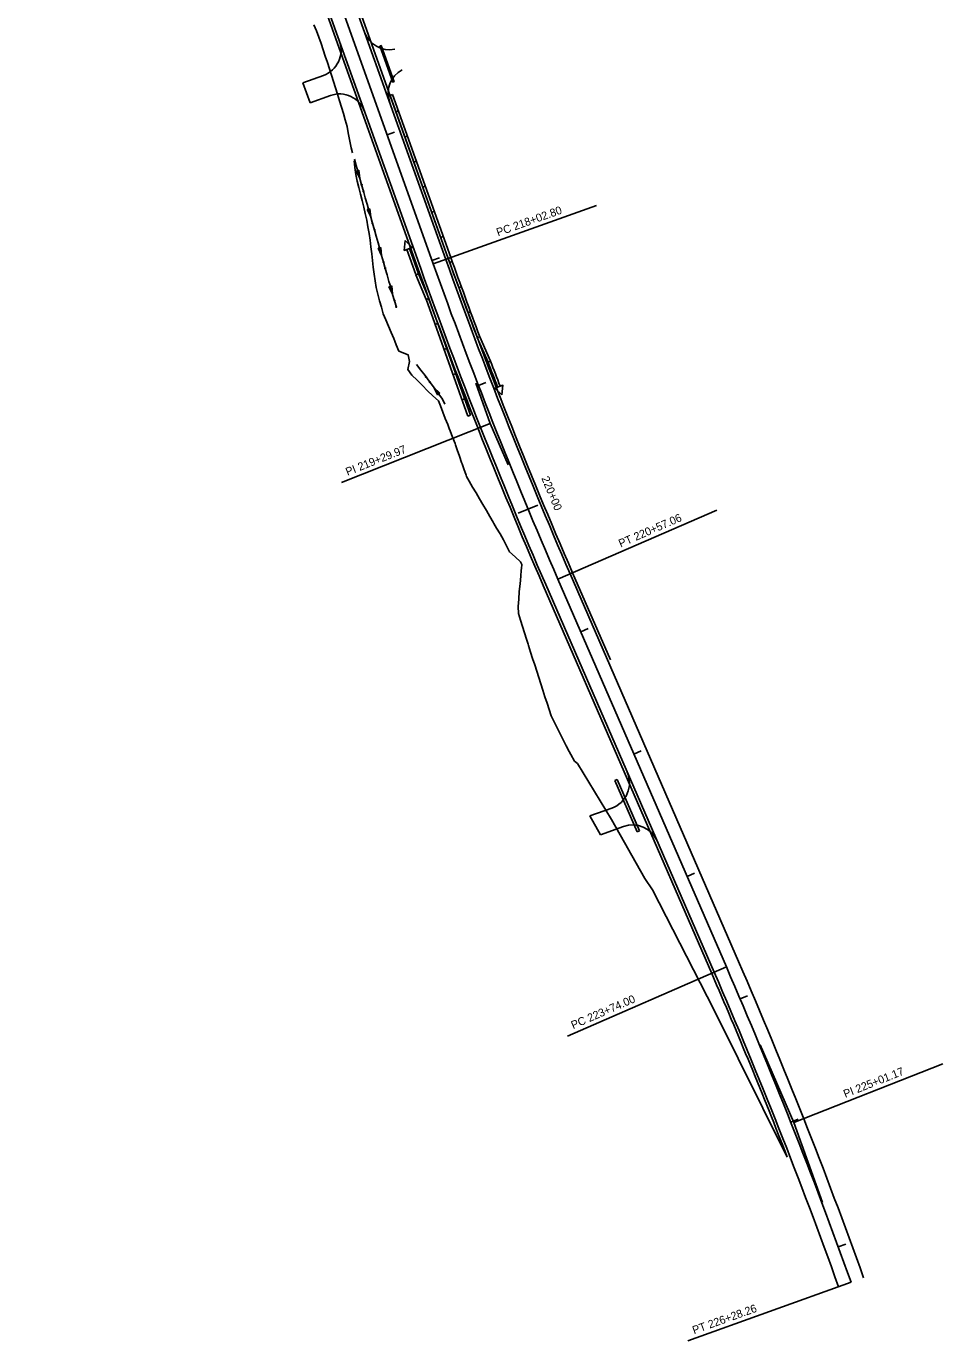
# Model space of a CAD drawing. Extents: x 1051958 to 1052837, y 395840 to 397825.
# Drawn here: x 1052150 to 1052837, y 395840 to 396826 of the extents above; entities that cross this region are included whole.
import ezdxf

# ---------------------------------------------------------------- set-up
doc = ezdxf.new("R2010")
doc.units = 0
for name, color, linetype in [('MOT_PCCB', 7, 'Continuous'), ('MOT_TIAB', 7, 'Continuous'), ('R_Drainage_Temporary', 7, 'Continuous'), ('R_Horz Alg Annot_Detour', 7, 'Continuous'), ('R_Horz Alg Stationing_Detour', 7, 'Continuous'), ('R_Horz Alg_Detour', 7, 'Continuous'), ('R_Proposed Const Limits', 7, 'Continuous'), ('R_Proposed Road_Detour', 7, 'Continuous'), ('R_Shld_Detour', 7, 'Continuous'), ('R_Special Ditch', 7, 'Continuous')]:
    doc.layers.add(name, color=color, linetype=linetype)

msp = doc.modelspace()

# ---------------------------------------------------------------- linework, layer by layer
at = {"layer": 'MOT_PCCB'}
for p, q in [((1052422.41, 396773.92), (1052424.29, 396774.59)), ((1052422.41, 396773.92), (1052466.12, 396651.7)), ((1052424.29, 396774.59), (1052468, 396652.38)), ((1052426.79, 396761.68), (1052428.67, 396762.35)), ((1052433.52, 396742.85), (1052435.41, 396743.52)), ((1052440.26, 396724.02), (1052442.14, 396724.69)), ((1052446.99, 396705.18), (1052448.88, 396705.86)), ((1052453.73, 396686.35), (1052455.61, 396687.02)), ((1052460.46, 396667.52), (1052462.34, 396668.19)), ((1052441.84, 396639.62), (1052435.1, 396658.45)), ((1052443.72, 396640.29), (1052436.99, 396659.12)), ((1052467.2, 396648.69), (1052469.08, 396649.36)), ((1052443.72, 396640.29), (1052441.84, 396639.62)), ((1052443.72, 396640.29), (1052441.88, 396639.53)), ((1052449.55, 396621.03), (1052441.88, 396639.53)), ((1052451.4, 396621.8), (1052443.72, 396640.29)), ((1052473.93, 396629.86), (1052475.81, 396630.53)), ((1052451.4, 396621.8), (1052449.52, 396621.12)), ((1052480.83, 396533.56), (1052449.52, 396621.12)), ((1052451.4, 396621.8), (1052449.55, 396621.03)), ((1052482.71, 396534.23), (1052451.4, 396621.8)), ((1052480.9, 396611.11), (1052482.78, 396611.78)), ((1052458.13, 396602.97), (1052456.25, 396602.29)), ((1052464.87, 396584.13), (1052462.98, 396583.46)), ((1052487.89, 396592.37), (1052489.78, 396593.04)), ((1052487.89, 396592.37), (1052495.93, 396574)), ((1052489.78, 396593.04), (1052497.82, 396574.68)), ((1052495.93, 396574), (1052497.82, 396574.68)), ((1052471.6, 396565.3), (1052469.72, 396564.63)), ((1052503.13, 396555.34), (1052505.01, 396556.01)), ((1052478.34, 396546.47), (1052476.45, 396545.8)), ((1052482.71, 396534.23), (1052480.83, 396533.56))]:
    msp.add_line(p, q, dxfattribs=at)
for radius, start, end in [(3807.72, 199.67806, 200.62965), (3805.72, 199.67806, 200.62965), (3806.72, 200.93048, 201.2316), (3804.72, 200.93114, 201.23242)]:
    msp.add_arc((1056051.46, 397933.9), radius, start, end, dxfattribs=at)
at = {"layer": 'MOT_TIAB'}
for points in [[(1052433.8, 396665.07), (1052439, 396659.84), (1052433.09, 396657.73)], [(1052506.32, 396549.39), (1052501.12, 396554.62), (1052507.02, 396556.73)]]:
    msp.add_lwpolyline(points, close=True, dxfattribs=at)
at = {"layer": 'R_Drainage_Temporary'}
for p, q in [((1052414.79, 396811.15), (1052415.74, 396811.49)), ((1052414.79, 396811.15), (1052424.62, 396783.86)), ((1052415.74, 396811.49), (1052425.56, 396784.2)), ((1052424.62, 396783.86), (1052425.56, 396784.2)), ((1052592.84, 396261.23), (1052591, 396260.44)), ((1052607.74, 396221.92), (1052591, 396260.44)), ((1052609.58, 396222.72), (1052592.84, 396261.23)), ((1052607.74, 396221.92), (1052609.58, 396222.72))]:
    msp.add_line(p, q, dxfattribs=at)
at = {"layer": 'R_Horz Alg Annot_Detour'}
for p, q in [((1052497.64, 396527.91), (1052486.79, 396558.25)), ((1052497.64, 396527.91), (1052511.08, 396497)), ((1052725.37, 396003.97), (1052700.02, 396062.29)), ((1052725.37, 396003.97), (1052746.78, 395944.1))]:
    msp.add_line(p, q, dxfattribs=at)
for points in [[(1052454.82, 396647.66), (1052577.23, 396691.44)], [(1052497.64, 396527.91), (1052386.06, 396483.77)], [(1052548.34, 396411.28), (1052667.56, 396463.1)], [(1052674.68, 396120.61), (1052555.45, 396068.79)], [(1052725.37, 396003.97), (1052836.96, 396048.12)], [(1052768.2, 395884.22), (1052645.79, 395840.45)]]:
    msp.add_lwpolyline(points, dxfattribs=at)
at = {"layer": 'R_Horz Alg Stationing_Detour'}
for p, q in [((1052610.82, 396282.57), (1052605.32, 396280.18)), ((1052650.68, 396190.86), (1052645.18, 396188.47)), ((1052690.48, 396099.08), (1052684.96, 396096.72)), ((1052728.57, 396006.45), (1052722.99, 396004.24)), ((1052764.22, 395912.86), (1052758.58, 395910.79))]:
    msp.add_line(p, q, dxfattribs=at)
for points in [[(1052425.85, 396746.48), (1052420.2, 396744.46)], [(1052459.53, 396652.32), (1052453.88, 396650.3)], [(1052494.31, 396558.73), (1052488.71, 396556.56)], [(1052533.37, 396466.85), (1052518.6, 396460.69)], [(1052570.96, 396374.28), (1052565.46, 396371.89)]]:
    msp.add_lwpolyline(points, dxfattribs=at)
at = {"layer": 'R_Horz Alg_Detour'}
for p, q in [((1052160.88, 397469.61), (1052454.82, 396647.66)), ((1052548.34, 396411.28), (1052674.68, 396120.61))]:
    msp.add_line(p, q, dxfattribs=at)
for centre, start, end in [((1056051.46, 397933.9), 199.67806, 203.49194), ((1049171.55, 394597.99), 19.67806, 23.49194)]:
    msp.add_arc(centre, 3819.72, start, end, dxfattribs=at)
at = {"layer": 'R_Proposed Const Limits'}
msp.add_line((1052665.37, 396088.72), (1052720.38, 395978.04), dxfattribs=at)
for points in [[(1052365.33, 396826.85), (1052367.38, 396822.27), (1052369.1, 396817.58), (1052370.81, 396812.88), (1052372.36, 396808.13), (1052373.87, 396803.36), (1052375.42, 396798.6), (1052376.97, 396793.84), (1052378.47, 396789.07), (1052380.05, 396784.32), (1052381.57, 396779.56), (1052383.08, 396774.79), (1052384.54, 396770), (1052385.99, 396765.21), (1052387.44, 396760.42), (1052388.88, 396755.62), (1052390.15, 396750.77), (1052391.13, 396745.81), (1052392.04, 396740.82), (1052392.95, 396735.84), (1052393.14, 396734.78), (1052394.25, 396730.99)], [(1052395.41, 396724.88), (1052396.07, 396719.81), (1052396.86, 396714.78), (1052397.76, 396709.79), (1052398.96, 396704.91), (1052400.18, 396700.04), (1052401.41, 396695.17), (1052402.64, 396690.3), (1052403.86, 396685.42), (1052404.94, 396680.5), (1052405.84, 396675.51), (1052406.73, 396670.52), (1052407.47, 396665.47), (1052408.08, 396660.38), (1052408.68, 396655.28), (1052409.27, 396650.18), (1052409.84, 396645.08), (1052410.49, 396640), (1052411.27, 396634.97), (1052412.03, 396629.92), (1052412.41, 396627.84), (1052413.23, 396624.97), (1052414.62, 396620.09), (1052415.96, 396615.2), (1052417.31, 396610.3), (1052419.27, 396605.62), (1052421.24, 396600.95), (1052423.2, 396596.28), (1052425.16, 396591.61), (1052425.96, 396589.69), (1052425.96, 396589.68), (1052427.11, 396586.94), (1052429.06, 396582.26), (1052436.07, 396579.48), (1052436.98, 396574.42), (1052435.8, 396568.58), (1052438.77, 396564.29), (1052442.74, 396560.39), (1052446.69, 396556.49), (1052450.58, 396552.57), (1052454.44, 396548.65), (1052458.67, 396544.95)], [(1052458.67, 396544.95), (1052460.17, 396541.27), (1052462.01, 396536.58), (1052463.84, 396531.88), (1052465.67, 396527.18), (1052466.8, 396524.31), (1052467.51, 396522.48), (1052469.33, 396517.79), (1052471.16, 396513.08), (1052471.54, 396512.09), (1052472.86, 396508.33), (1052474.48, 396503.55), (1052476.11, 396498.77), (1052476.45, 396497.76), (1052477.72, 396493.99), (1052479.46, 396489.25), (1052479.88, 396488.27), (1052481.78, 396484.74), (1052484.37, 396480.36), (1052486.96, 396475.97), (1052489.54, 396471.58), (1052492.11, 396467.19), (1052494.68, 396462.8), (1052497.25, 396458.41), (1052499.81, 396454.01), (1052500.35, 396453.08), (1052502.36, 396449.62), (1052504.9, 396445.23), (1052507.44, 396440.84), (1052509.78, 396436.36), (1052512.09, 396431.87), (1052516.18, 396428.14), (1052520.25, 396424.41), (1052521.19, 396422.25)], [(1052521.19, 396422.25), (1052520.94, 396419.24), (1052520.84, 396418.03), (1052520.47, 396413.56), (1052519.91, 396407.84), (1052519.34, 396402.1), (1052518.93, 396396.44), (1052518.54, 396390.82), (1052518.83, 396385.5), (1052520.29, 396380.68), (1052521.77, 396375.87), (1052523.31, 396371.09), (1052524.85, 396366.31), (1052526.02, 396362.56), (1052526.35, 396361.5), (1052527.86, 396356.71), (1052529.39, 396351.92), (1052531.04, 396347.19), (1052532.54, 396342.39), (1052534.06, 396337.6), (1052535.59, 396332.81), (1052537.13, 396328.03), (1052538.64, 396323.23), (1052540.15, 396318.44), (1052541.66, 396313.64), (1052543.29, 396308.9), (1052545.56, 396304.43), (1052547.82, 396299.96), (1052550.04, 396295.48), (1052552.26, 396290.99), (1052554.47, 396286.5), (1052556.72, 396282.02), (1052559.28, 396277.69), (1052559.57, 396277.2), (1052560.86, 396275.01)], [(1052560.86, 396275.01), (1052563.12, 396273.05), (1052567.39, 396266.08), (1052588.59, 396231.18), (1052613.6, 396187.03), (1052619.23, 396178.42), (1052665.37, 396088.72)]]:
    msp.add_lwpolyline(points, dxfattribs=at)
at = {"layer": 'R_Proposed Road_Detour'}
for p, q in [((1052170.29, 397472.97), (1052464.23, 396651.03)), ((1052151.46, 397466.24), (1052445.4, 396644.3)), ((1052151.46, 397466.24), (1052445.4, 396644.3)), ((1052357.11, 396783.49), (1052372.42, 396788.97)), ((1052357.11, 396783.49), (1052362.5, 396768.43)), ((1052362.5, 396768.43), (1052377.81, 396773.9)), ((1052539.17, 396407.29), (1052665.51, 396116.62)), ((1052557.51, 396415.26), (1052683.85, 396124.59)), ((1052588.74, 396239.73), (1052572.31, 396233.86)), ((1052572.31, 396233.86), (1052580.29, 396219.72)), ((1052597.64, 396225.92), (1052580.29, 396219.72))]:
    msp.add_line(p, q, dxfattribs=at)
for centre, radius, start, end in [((1052422.11, 396828.22), 20, 199.67806, 281.05113), ((1052365.69, 396807.8), 20, 289.67806, 19.67806), ((1052440.97, 396775.49), 20, 118.30498, 199.67806), ((1052384.55, 396755.07), 20, 19.67806, 109.67806), ((1056051.46, 397933.9), 3829.72, 199.67806, 203.49194), ((1056051.46, 397933.9), 3809.72, 199.67806, 203.49194), ((1052582, 396258.56), 20, 289.67806, 23.49194), ((1052604.38, 396207.09), 20, 23.49194, 109.67806), ((1049171.55, 394597.99), 3829.72, 19.67806, 23.49194), ((1049171.55, 394597.99), 3809.72, 19.67806, 23.49194)]:
    msp.add_arc(centre, radius, start, end, dxfattribs=at)
at = {"layer": 'R_Shld_Detour'}
for p, q in [((1052172.17, 397473.65), (1052466.12, 396651.7)), ((1052149.58, 397465.56), (1052443.52, 396643.62)), ((1052559.34, 396416.06), (1052587.74, 396350.73)), ((1052537.33, 396406.5), (1052663.67, 396115.82))]:
    msp.add_line(p, q, dxfattribs=at)
for centre, radius, start, end in [((1056051.46, 397933.9), 3831.72, 199.67806, 203.49194), ((1056051.46, 397933.9), 3807.72, 199.67806, 203.49194), ((1049171.55, 394597.99), 3807.72, 21.24979, 23.49194)]:
    msp.add_arc(centre, radius, start, end, dxfattribs=at)
at = {"layer": 'R_Special Ditch'}
for p, q in [((1052399.13, 396717.81), (1052397.09, 396717.24)), ((1052397.09, 396717.24), (1052399.74, 396711.75)), ((1052399.74, 396711.75), (1052399.13, 396717.81)), ((1052407.3, 396688.91), (1052405.27, 396688.33)), ((1052405.27, 396688.33), (1052407.92, 396682.85)), ((1052407.92, 396682.85), (1052407.3, 396688.91)), ((1052415.48, 396660.01), (1052413.44, 396659.43)), ((1052413.44, 396659.43), (1052416.09, 396653.94)), ((1052416.09, 396653.94), (1052415.48, 396660.01)), ((1052423.65, 396631.11), (1052421.62, 396630.52)), ((1052421.62, 396630.52), (1052424.29, 396625.05)), ((1052424.29, 396625.05), (1052423.65, 396631.11)), ((1052455.26, 396555.03), (1052457.99, 396549.58)), ((1052459.69, 396550.84), (1052455.26, 396555.03)), ((1052457.99, 396549.58), (1052459.69, 396550.84))]:
    msp.add_line(p, q, dxfattribs=at)
for points in [[(1052395.66, 396726.19), (1052397.03, 396721.37), (1052398.39, 396716.54), (1052399.75, 396711.72), (1052401.12, 396706.9), (1052402.48, 396702.08), (1052403.84, 396697.25), (1052405.21, 396692.43), (1052406.57, 396687.61), (1052407.94, 396682.79), (1052409.3, 396677.96), (1052410.66, 396673.14), (1052412.03, 396668.32), (1052413.39, 396663.5), (1052414.75, 396658.67), (1052416.12, 396653.85), (1052417.48, 396649.03), (1052418.84, 396644.21), (1052420.21, 396639.38), (1052421.58, 396634.55), (1052422.14, 396632.55), (1052422.96, 396629.69), (1052424.35, 396624.82), (1052425.75, 396619.96), (1052427.14, 396615.1)], [(1052395.66, 396726.19), (1052397.03, 396721.37), (1052398.39, 396716.54), (1052399.74, 396711.75)], [(1052403.83, 396697.32), (1052403.84, 396697.28)], [(1052403.84, 396697.28), (1052403.84, 396697.25), (1052405.21, 396692.43), (1052406.57, 396687.61), (1052407.92, 396682.85)], [(1052412, 396668.41), (1052412.01, 396668.38)], [(1052412.01, 396668.38), (1052412.03, 396668.32), (1052413.39, 396663.5), (1052414.75, 396658.67), (1052416.09, 396653.94)], [(1052420.17, 396639.51), (1052420.18, 396639.47)], [(1052420.18, 396639.47), (1052420.21, 396639.38), (1052421.58, 396634.55), (1052422.14, 396632.55), (1052422.96, 396629.69), (1052424.29, 396625.05)], [(1052442.34, 396572.27), (1052445.51, 396568.07), (1052448.67, 396563.87), (1052451.81, 396559.67), (1052454.94, 396555.47), (1052458.06, 396551.26), (1052461.16, 396547.06), (1052461.82, 396546.17), (1052463.49, 396542.56)], [(1052446.26, 396567.07), (1052445.51, 396568.07), (1052442.34, 396572.27)], [(1052446.28, 396567.04), (1052446.26, 396567.07)], [(1052463.49, 396542.56), (1052461.82, 396546.17), (1052461.16, 396547.06), (1052458.06, 396551.26), (1052455.26, 396555.03)]]:
    msp.add_lwpolyline(points, dxfattribs=at)
for centre in [(1052401.14, 396706.95), (1052402.5, 396702.13), (1052409.31, 396678.04), (1052410.68, 396673.22), (1052417.49, 396649.14), (1052418.85, 396644.32), (1052425.7, 396620.24), (1052427.09, 396615.43), (1052449.24, 396563.04), (1052452.25, 396559.02)]:
    msp.add_circle(centre, 0.375, dxfattribs=at)

# ---------------------------------------------------------------- texts
at = {"layer": 'R_Horz Alg Annot_Detour'}
for s, rotation, p in [('PC 218+02.80', 19.67806, (1052503.44, 396668.24)), ('PI 219+29.97', 21.585, (1052390.53, 396488.77)), ('PT 220+57.06', 23.49194, (1052595.41, 396435.01)), ('PC 223+74.00', 23.49194, (1052559.76, 396073.93)), ('PI 225+01.17', 21.585, (1052763.88, 396022.43)), ('PT 226+28.26', 19.67806, (1052650.43, 395845.29))]:
    msp.add_text(s, height=6, rotation=rotation, dxfattribs=at).set_placement(p)
at = {"layer": 'R_Horz Alg Stationing_Detour'}
msp.add_text('220+00', height=6, rotation=292.63612, dxfattribs=at).set_placement((1052535.81, 396486.99))

doc.saveas('drawing.dxf')
